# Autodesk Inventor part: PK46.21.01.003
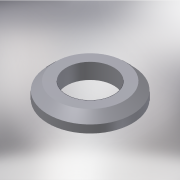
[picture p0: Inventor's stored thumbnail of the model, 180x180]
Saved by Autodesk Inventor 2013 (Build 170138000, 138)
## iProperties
Created: 2005-04
Part Number: PK46.21.01.003
Material: Steel, Mild
Document SubType Name: Modeling
Designer: salex
Manufacturer: Standard
Standards Organization: Custom
Density: 7.86 g/cm^3
Author: salex
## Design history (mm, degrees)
sketch "Эскиз1"
  geometry: C1 r 45 at (0, 0); C2 r 80 at (0, 0)
  constraints: 2 centre point, 1 coincident, 1 other
  dimensions: "d0" = 160 diameter of C2; "d1" = 90 diameter of C1
extrude "Выдавливание1" new body sketch "Эскиз1" distance "d2" = 30; taper "d3" = 0 deg
chamfer "Фаска1" distance "d4" = 15; stored, may be unused: second distance "d5" = 2, angle "d6" = 45 deg
body "Solid1"
